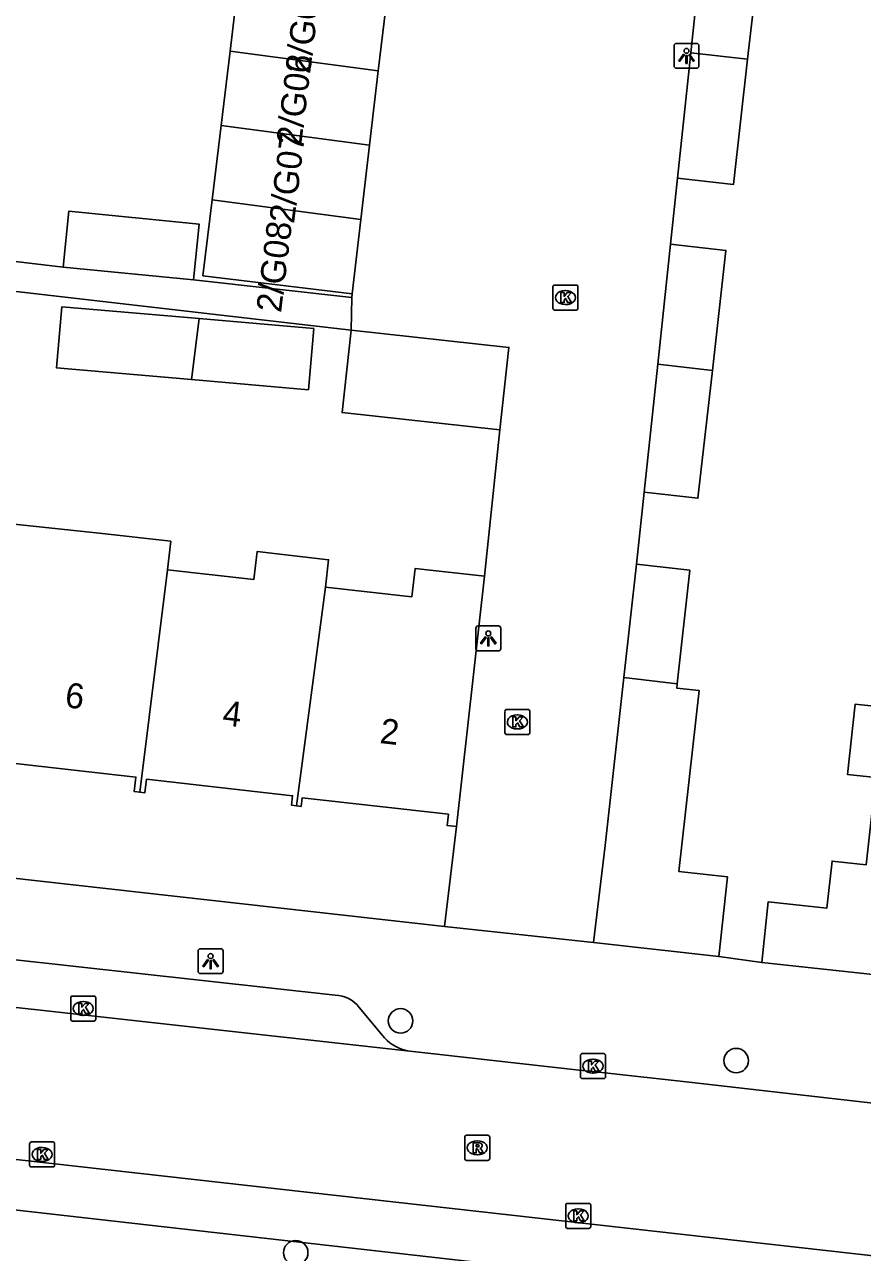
# Model space of a CAD drawing. Extents: x 162082 to 163393, y 388091 to 388632.
# Drawn here: x 162920.79 to 162954.3, y 388448.74 to 388497.83 of the extents above; entities that cross this region are included whole.
import ezdxf

# ---------------------------------------------------------------- set-up
doc = ezdxf.new("R2010")
doc.units = 0
for name, color, linetype in [('IMGEO_Boom', 7, 'Continuous'), ('IMGEO_Kolk', 7, 'Continuous'), ('IMGEO_Lichtpunt', 7, 'Continuous'), ('IMGEO_Pand', 7, 'Continuous'), ('IMGEO_Pand_nummerreeks', 7, 'Continuous'), ('IMGEO_Rijbaan_lokaal_open', 7, 'Continuous'), ('IMGEO_Rioolput', 7, 'Continuous'), ('IMGEO_Voetpad_open', 7, 'Continuous')]:
    doc.layers.add(name, color=color, linetype=linetype)

msp = doc.modelspace()

# ---------------------------------------------------------------- linework, layer by layer
at = {"layer": 'IMGEO_Boom'}
for centre in [(162935.83, 388457.998), (162949.253, 388456.41), (162931.639, 388448.731)]:
    msp.add_circle(centre, 0.489, dxfattribs=at)
at = {"layer": 'IMGEO_Kolk'}
for p, q in [((162941.925, 388486.486), (162941.925, 388487.338)), ((162942, 388487.412), (162942.852, 388487.412)), ((162942.413, 388487.192), (162942.438, 388487.192)), ((162942.926, 388487.338), (162942.926, 388486.486)), ((162942.852, 388486.412), (162942, 388486.412)), ((162942.436, 388486.632), (162942.411, 388486.632)), ((162940.001, 388469.52), (162940.001, 388470.372)), ((162940.076, 388470.446), (162940.928, 388470.446)), ((162940.489, 388470.226), (162940.514, 388470.226)), ((162941.002, 388470.372), (162941.002, 388469.52)), ((162940.512, 388469.666), (162940.487, 388469.666)), ((162940.928, 388469.446), (162940.076, 388469.446)), ((162922.641, 388458.065), (162922.641, 388458.917)), ((162922.716, 388458.991), (162923.568, 388458.991)), ((162923.129, 388458.771), (162923.154, 388458.771)), ((162923.642, 388458.917), (162923.642, 388458.065)), ((162923.152, 388458.211), (162923.127, 388458.211)), ((162923.568, 388457.991), (162922.716, 388457.991)), ((162943.025, 388455.763), (162943.025, 388456.615)), ((162943.1, 388456.689), (162943.952, 388456.689)), ((162943.513, 388456.469), (162943.538, 388456.469)), ((162944.026, 388456.615), (162944.026, 388455.763)), ((162943.536, 388455.909), (162943.511, 388455.909)), ((162943.952, 388455.689), (162943.1, 388455.689)), ((162920.996, 388452.233), (162920.996, 388453.085)), ((162921.071, 388453.159), (162921.923, 388453.159)), ((162921.484, 388452.939), (162921.509, 388452.939)), ((162921.997, 388453.085), (162921.997, 388452.233)), ((162921.507, 388452.379), (162921.482, 388452.379)), ((162921.923, 388452.159), (162921.071, 388452.159)), ((162942.434, 388449.775), (162942.434, 388450.627)), ((162942.509, 388450.701), (162943.361, 388450.701)), ((162942.922, 388450.481), (162942.947, 388450.481)), ((162943.435, 388450.627), (162943.435, 388449.775)), ((162942.945, 388449.921), (162942.92, 388449.921)), ((162943.361, 388449.701), (162942.509, 388449.701))]:
    msp.add_line(p, q, dxfattribs=at)
for points in [[(162941.925, 388486.486), (162941.925, 388487.338)], [(162942, 388487.412), (162942.852, 388487.412)], [(162942.926, 388487.338), (162942.926, 388486.486)], [(162942.246, 388487.112), (162942.369, 388487.112), (162942.369, 388486.961), (162942.499, 388487.112), (162942.663, 388487.112), (162942.517, 388486.961), (162942.67, 388486.712), (162942.518, 388486.712), (162942.433, 388486.876), (162942.369, 388486.809), (162942.369, 388486.712), (162942.246, 388486.712), (162942.246, 388487.112)], [(162942.852, 388486.412), (162942, 388486.412)], [(162940.001, 388469.52), (162940.001, 388470.372)], [(162940.076, 388470.446), (162940.928, 388470.446)], [(162940.322, 388470.146), (162940.445, 388470.146), (162940.445, 388469.995), (162940.575, 388470.146), (162940.739, 388470.146), (162940.593, 388469.995), (162940.746, 388469.746), (162940.594, 388469.746), (162940.509, 388469.91), (162940.445, 388469.843), (162940.445, 388469.746), (162940.322, 388469.746), (162940.322, 388470.146)], [(162941.002, 388470.372), (162941.002, 388469.52)], [(162940.928, 388469.446), (162940.076, 388469.446)], [(162922.641, 388458.065), (162922.641, 388458.917)], [(162922.716, 388458.991), (162923.568, 388458.991)], [(162922.962, 388458.691), (162923.085, 388458.691), (162923.085, 388458.54), (162923.215, 388458.691), (162923.379, 388458.691), (162923.233, 388458.54), (162923.386, 388458.291), (162923.234, 388458.291), (162923.149, 388458.455), (162923.085, 388458.388), (162923.085, 388458.291), (162922.962, 388458.291), (162922.962, 388458.691)], [(162923.642, 388458.917), (162923.642, 388458.065)], [(162923.568, 388457.991), (162922.716, 388457.991)], [(162943.025, 388455.763), (162943.025, 388456.615)], [(162943.1, 388456.689), (162943.952, 388456.689)], [(162943.346, 388456.389), (162943.469, 388456.389), (162943.469, 388456.238), (162943.599, 388456.389), (162943.763, 388456.389), (162943.617, 388456.238), (162943.77, 388455.989), (162943.618, 388455.989), (162943.533, 388456.153), (162943.469, 388456.086), (162943.469, 388455.989), (162943.346, 388455.989), (162943.346, 388456.389)], [(162944.026, 388456.615), (162944.026, 388455.763)], [(162943.952, 388455.689), (162943.1, 388455.689)], [(162920.996, 388452.233), (162920.996, 388453.085)], [(162921.071, 388453.159), (162921.923, 388453.159)], [(162921.317, 388452.859), (162921.44, 388452.859), (162921.44, 388452.708), (162921.57, 388452.859), (162921.734, 388452.859), (162921.588, 388452.708), (162921.741, 388452.459), (162921.589, 388452.459), (162921.504, 388452.623), (162921.44, 388452.556), (162921.44, 388452.459), (162921.317, 388452.459), (162921.317, 388452.859)], [(162921.997, 388453.085), (162921.997, 388452.233)], [(162921.923, 388452.159), (162921.071, 388452.159)], [(162942.434, 388449.775), (162942.434, 388450.627)], [(162942.509, 388450.701), (162943.361, 388450.701)], [(162942.755, 388450.401), (162942.878, 388450.401), (162942.878, 388450.25), (162943.008, 388450.401), (162943.172, 388450.401), (162943.026, 388450.25), (162943.179, 388450.001), (162943.027, 388450.001), (162942.942, 388450.165), (162942.878, 388450.098), (162942.878, 388450.001), (162942.755, 388450.001), (162942.755, 388450.401)], [(162943.435, 388450.627), (162943.435, 388449.775)], [(162943.361, 388449.701), (162942.509, 388449.701)]]:
    msp.add_lwpolyline(points, dxfattribs=at)
for centre, start, end in [((162942.002, 388487.336), 91.552, 178.448), ((162942.002, 388487.336), 91.552, 178.448), ((162942.85, 388487.336), 1.552, 88.448), ((162942.85, 388487.336), 1.552, 88.448), ((162942.002, 388486.488), 181.552, 268.448), ((162942.002, 388486.488), 181.552, 268.448), ((162942.85, 388486.488), 271.552, 358.448), ((162942.85, 388486.488), 271.552, 358.448), ((162940.078, 388470.37), 91.552, 178.448), ((162940.078, 388470.37), 91.552, 178.448), ((162940.926, 388470.37), 1.552, 88.448), ((162940.926, 388470.37), 1.552, 88.448), ((162940.078, 388469.522), 181.552, 268.448), ((162940.078, 388469.522), 181.552, 268.448), ((162940.926, 388469.522), 271.552, 358.448), ((162940.926, 388469.522), 271.552, 358.448), ((162922.718, 388458.915), 91.552, 178.448), ((162922.718, 388458.915), 91.552, 178.448), ((162923.566, 388458.915), 1.552, 88.448), ((162923.566, 388458.915), 1.552, 88.448), ((162922.718, 388458.067), 181.552, 268.448), ((162922.718, 388458.067), 181.552, 268.448), ((162923.566, 388458.067), 271.552, 358.448), ((162923.566, 388458.067), 271.552, 358.448), ((162943.102, 388456.613), 91.552, 178.448), ((162943.102, 388456.613), 91.552, 178.448), ((162943.95, 388456.613), 1.552, 88.448), ((162943.95, 388456.613), 1.552, 88.448), ((162943.102, 388455.765), 181.552, 268.448), ((162943.102, 388455.765), 181.552, 268.448), ((162943.95, 388455.765), 271.552, 358.448), ((162943.95, 388455.765), 271.552, 358.448), ((162921.073, 388453.083), 91.552, 178.448), ((162921.073, 388453.083), 91.552, 178.448), ((162921.921, 388453.083), 1.552, 88.448), ((162921.921, 388453.083), 1.552, 88.448), ((162921.073, 388452.235), 181.552, 268.448), ((162921.073, 388452.235), 181.552, 268.448), ((162921.921, 388452.235), 271.552, 358.448), ((162921.921, 388452.235), 271.552, 358.448), ((162942.511, 388450.625), 91.552, 178.448), ((162942.511, 388450.625), 91.552, 178.448), ((162943.359, 388450.625), 1.552, 88.448), ((162943.359, 388450.625), 1.552, 88.448), ((162942.511, 388449.777), 181.552, 268.448), ((162942.511, 388449.777), 181.552, 268.448), ((162943.359, 388449.777), 271.552, 358.448), ((162943.359, 388449.777), 271.552, 358.448)]:
    msp.add_arc(centre, 0.0765, start, end, dxfattribs=at)
for centre, major_axis, ratio, start_param, end_param in [((162942.412, 388486.912), (-0.387, 0.002), 0.722429, 4.712389, 7.853982), ((162942.437, 388486.912), (-0.39, 0.002), 0.717154, 1.570796, 4.712389), ((162940.488, 388469.946), (-0.387, 0.002), 0.722429, 4.712389, 7.853982), ((162940.513, 388469.946), (-0.39, 0.002), 0.717154, 1.570796, 4.712389), ((162923.128, 388458.491), (-0.387, 0.002), 0.722429, 4.712389, 7.853982), ((162923.153, 388458.491), (-0.39, 0.002), 0.717154, 1.570796, 4.712389), ((162943.512, 388456.189), (-0.387, 0.002), 0.722429, 4.712389, 7.853982), ((162943.537, 388456.189), (-0.39, 0.002), 0.717154, 1.570796, 4.712389), ((162921.483, 388452.659), (-0.387, 0.002), 0.722429, 4.712389, 7.853982), ((162921.508, 388452.659), (-0.39, 0.002), 0.717154, 1.570796, 4.712389), ((162942.921, 388450.201), (-0.387, 0.002), 0.722429, 4.712389, 7.853982), ((162942.946, 388450.201), (-0.39, 0.002), 0.717154, 1.570796, 4.712389)]:
    msp.add_ellipse(centre, major_axis=major_axis, ratio=ratio, start_param=start_param, end_param=end_param, dxfattribs=at)
at = {"layer": 'IMGEO_Lichtpunt'}
for p, q in [((162946.767, 388496.979), (162946.767, 388496.172)), ((162946.767, 388496.979), (162946.767, 388496.172)), ((162947.669, 388497.074), (162946.861, 388497.074)), ((162947.669, 388497.074), (162946.861, 388497.074)), ((162947.763, 388496.172), (162947.763, 388496.979)), ((162947.763, 388496.172), (162947.763, 388496.979)), ((162946.861, 388496.078), (162947.669, 388496.078)), ((162946.861, 388496.078), (162947.669, 388496.078)), ((162938.841, 388473.69), (162938.841, 388472.883)), ((162938.841, 388473.69), (162938.841, 388472.883)), ((162939.743, 388473.785), (162938.935, 388473.785)), ((162939.743, 388473.785), (162938.935, 388473.785)), ((162939.837, 388472.883), (162939.837, 388473.69)), ((162939.837, 388472.883), (162939.837, 388473.69)), ((162938.935, 388472.789), (162939.743, 388472.789)), ((162938.935, 388472.789), (162939.743, 388472.789)), ((162927.736, 388460.788), (162927.736, 388459.981)), ((162927.736, 388460.788), (162927.736, 388459.981)), ((162928.638, 388460.883), (162927.83, 388460.883)), ((162928.638, 388460.883), (162927.83, 388460.883)), ((162928.732, 388459.981), (162928.732, 388460.788)), ((162928.732, 388459.981), (162928.732, 388460.788)), ((162927.83, 388459.887), (162928.638, 388459.887)), ((162927.83, 388459.887), (162928.638, 388459.887))]:
    msp.add_line(p, q, dxfattribs=at)
for points in [[(162947.141, 388496.643), (162947.18, 388496.615), (162946.992, 388496.353), (162946.954, 388496.38), (162947.141, 388496.643)], [(162947.243, 388496.595), (162947.29, 388496.595), (162947.29, 388496.273), (162947.243, 388496.273), (162947.243, 388496.595)], [(162947.353, 388496.615), (162947.391, 388496.642), (162947.578, 388496.38), (162947.539, 388496.352), (162947.353, 388496.615)], [(162939.215, 388473.354), (162939.254, 388473.326), (162939.066, 388473.064), (162939.028, 388473.091), (162939.215, 388473.354)], [(162939.317, 388473.306), (162939.364, 388473.306), (162939.364, 388472.984), (162939.317, 388472.984), (162939.317, 388473.306)], [(162939.427, 388473.326), (162939.465, 388473.353), (162939.652, 388473.091), (162939.613, 388473.063), (162939.427, 388473.326)], [(162928.11, 388460.452), (162928.149, 388460.424), (162927.961, 388460.162), (162927.923, 388460.189), (162928.11, 388460.452)], [(162928.212, 388460.404), (162928.259, 388460.404), (162928.259, 388460.082), (162928.212, 388460.082), (162928.212, 388460.404)], [(162928.322, 388460.424), (162928.36, 388460.451), (162928.547, 388460.189), (162928.508, 388460.161), (162928.322, 388460.424)]]:
    msp.add_lwpolyline(points, dxfattribs=at)
for centre in [(162947.266, 388496.777), (162939.34, 388473.488), (162928.235, 388460.586)]:
    msp.add_circle(centre, 0.0994, dxfattribs=at)
for centre, start, end in [((162946.861, 388496.979), 90, 180), ((162946.861, 388496.979), 90, 180), ((162947.669, 388496.979), 0, 90), ((162947.669, 388496.979), 0, 90), ((162946.861, 388496.172), 180, 270), ((162946.861, 388496.172), 180, 270), ((162947.669, 388496.172), 270, 0), ((162947.669, 388496.172), 270, 360), ((162938.935, 388473.69), 90, 180), ((162938.935, 388473.69), 90, 180), ((162939.743, 388473.69), 0, 90), ((162939.743, 388473.69), 0, 90), ((162938.935, 388472.883), 180, 270), ((162938.935, 388472.883), 180, 270), ((162939.743, 388472.883), 270, 0), ((162939.743, 388472.883), 270, 360), ((162927.83, 388460.788), 90, 180), ((162927.83, 388460.788), 90, 180), ((162928.638, 388460.788), 0, 90), ((162928.638, 388460.788), 0, 90), ((162927.83, 388459.981), 180, 270), ((162927.83, 388459.981), 180, 270), ((162928.638, 388459.981), 270, 0), ((162928.638, 388459.981), 270, 360)]:
    msp.add_arc(centre, 0.0946, start, end, dxfattribs=at)
at = {"layer": 'IMGEO_Pand'}
for points in [[(162947.434, 388496.691), (162947.785, 388500), (162947.954, 388501.591)], [(162947.954, 388501.591), (162950.262, 388501.33), (162950.112, 388500), (162949.709, 388496.438)], [(162935.291, 388498.943), (162934.941, 388495.971)], [(162929.012, 388496.762), (162929.23, 388498.563)], [(162928.653, 388493.791), (162929.012, 388496.762)], [(162929.012, 388496.762), (162934.941, 388495.971)], [(162946.902, 388491.686), (162947.434, 388496.691)], [(162947.434, 388496.691), (162949.709, 388496.438)], [(162949.709, 388496.438), (162949.143, 388491.433), (162946.902, 388491.686)], [(162934.941, 388495.971), (162934.59, 388492.999)], [(162928.294, 388490.821), (162928.653, 388493.791)], [(162928.653, 388493.791), (162934.59, 388492.999)], [(162934.59, 388492.999), (162934.24, 388490.028)], [(162933.89, 388487.061), (162927.926, 388487.782), (162928.294, 388490.821)], [(162934.24, 388490.028), (162928.294, 388490.821)], [(162922.341, 388488.13), (162922.56, 388490.361), (162927.773, 388489.848), (162927.554, 388487.617)], [(162934.24, 388490.028), (162933.89, 388487.061)], [(162946.113, 388484.252), (162946.622, 388489.051)], [(162946.622, 388489.051), (162948.845, 388488.8), (162948.303, 388484.004)], [(162927.554, 388487.617), (162922.341, 388488.13)], [(162927.466, 388483.635), (162922.078, 388484.103), (162922.29, 388486.547), (162927.771, 388486.071)], [(162927.466, 388483.635), (162927.771, 388486.071)], [(162927.771, 388486.071), (162932.36, 388485.672), (162932.148, 388483.228), (162927.466, 388483.635)], [(162939.801, 388481.623), (162933.495, 388482.314), (162933.857, 388485.612)], [(162933.857, 388485.612), (162940.163, 388484.92), (162939.801, 388481.623)], [(162945.57, 388479.136), (162946.113, 388484.252)], [(162946.113, 388484.252), (162948.303, 388484.004)], [(162948.303, 388484.004), (162947.725, 388478.893), (162945.57, 388479.136)], [(162920.381, 388477.851), (162923.777, 388477.496), (162926.641, 388477.172), (162926.513, 388476.035)], [(162926.513, 388476.035), (162929.964, 388475.645), (162930.09, 388476.759), (162932.955, 388476.435), (162932.831, 388475.341)], [(162925.398, 388467.14), (162926.513, 388476.035)], [(162932.831, 388475.341), (162936.288, 388474.95), (162936.416, 388476.083), (162939.192, 388475.769)], [(162944.757, 388471.719), (162945.263, 388476.25)], [(162945.263, 388476.25), (162947.399, 388476.012), (162946.893, 388471.475)], [(162939.192, 388475.769), (162938.062, 388465.768)], [(162932.831, 388475.341), (162931.676, 388466.593)], [(162943.553, 388461.129), (162944.008, 388465.015), (162944.757, 388471.719)], [(162944.757, 388471.719), (162946.893, 388471.475)], [(162946.893, 388471.475), (162946.874, 388471.302), (162947.771, 388471.202), (162946.964, 388463.967), (162948.912, 388463.75), (162948.558, 388460.57)], [(162950.273, 388460.333), (162950.537, 388462.759), (162952.884, 388462.505), (162953.088, 388464.384), (162954.447, 388464.237), (162954.831, 388467.725), (162953.701, 388467.849), (162954.009, 388470.657), (162955.142, 388470.533)], [(162925.398, 388467.14), (162925.184, 388467.164), (162925.25, 388467.741), (162919.474, 388468.394), (162919.419, 388467.911), (162919.225, 388467.933)], [(162931.676, 388466.593), (162931.472, 388466.616), (162931.515, 388466.997), (162925.671, 388467.658), (162925.61, 388467.116), (162925.398, 388467.14)], [(162938.062, 388465.768), (162937.693, 388465.81), (162937.743, 388466.255), (162931.899, 388466.916), (162931.86, 388466.572), (162931.676, 388466.593)], [(162948.558, 388460.57), (162943.553, 388461.129)], [(162959.667, 388459.314), (162950.273, 388460.333)]]:
    msp.add_lwpolyline(points, dxfattribs=at)
at = {"layer": 'IMGEO_Rijbaan_lokaal_open'}
for points in [[(162946.902, 388491.686), (162946.622, 388489.051)], [(162933.857, 388485.612), (162933.887, 388486.915)], [(162933.89, 388487.061), (162933.887, 388486.915)], [(162939.192, 388475.769), (162939.801, 388481.623)], [(162945.57, 388479.136), (162945.263, 388476.25)], [(162937.585, 388461.764), (162938.062, 388465.768)], [(162936.199, 388456.79), (162886.097, 388462.347)], [(162943.553, 388461.129), (162937.585, 388461.764)], [(162936.199, 388456.79), (162937.278, 388456.67), (162942.976, 388456.033), (162943.878, 388455.932), (162947.378, 388455.541), (162967.209, 388453.279)], [(162904.56, 388454.238), (163001.108, 388443.395)]]:
    msp.add_lwpolyline(points, dxfattribs=at)
at = {"layer": 'IMGEO_Rioolput'}
for p, q in [((162938.398, 388452.496), (162938.398, 388453.348)), ((162938.473, 388453.422), (162939.325, 388453.422)), ((162939.399, 388453.348), (162939.399, 388452.496)), ((162938.886, 388453.202), (162938.911, 388453.202)), ((162939.325, 388452.422), (162938.473, 388452.422)), ((162938.909, 388452.642), (162938.884, 388452.642))]:
    msp.add_line(p, q, dxfattribs=at)
for points in [[(162938.398, 388452.496), (162938.398, 388453.348)], [(162938.473, 388453.422), (162939.325, 388453.422)], [(162939.399, 388453.348), (162939.399, 388452.496)], [(162938.987, 388453.12), (162938.735, 388453.122), (162938.735, 388452.722)], [(162938.735, 388452.722), (162938.859, 388452.722), (162938.859, 388452.884), (162938.87, 388452.884)], [(162938.913, 388453.041), (162938.859, 388453.041), (162938.859, 388452.96)], [(162938.859, 388452.96), (162938.911, 388452.96)], [(162938.917, 388452.855), (162938.988, 388452.722), (162939.128, 388452.722), (162939.063, 388452.848)], [(162939.325, 388452.422), (162938.473, 388452.422)]]:
    msp.add_lwpolyline(points, dxfattribs=at)
for centre, radius, start, end in [((162938.475, 388453.346), 0.0765, 91.552, 178.448), ((162938.475, 388453.346), 0.0765, 91.552, 178.448), ((162939.323, 388453.346), 0.0765, 1.552, 88.448), ((162939.323, 388453.346), 0.0765, 1.552, 88.448), ((162938.869, 388452.831), 0.0533, 26.0293, 88.6989), ((162938.895, 388453.149), 0.19, 274.7715, 282.9687), ((162938.919, 388452.945), 0.0964, 77.0061, 93.1865), ((162938.933, 388453.002), 0.0378, 276.6634, 79.6772), ((162938.986, 388453.01), 0.109, 350.3612, 89.416), ((162938.984, 388453.01), 0.112, 277.5842, 350.9817), ((162938.968, 388452.795), 0.108, 29.5134, 73.7905), ((162938.475, 388452.498), 0.0765, 181.552, 268.448), ((162938.475, 388452.498), 0.0765, 181.552, 268.448), ((162939.323, 388452.498), 0.0765, 271.552, 358.448), ((162939.323, 388452.498), 0.0765, 271.552, 358.448)]:
    msp.add_arc(centre, radius, start, end, dxfattribs=at)
for centre, major_axis, ratio, start_param, end_param in [((162938.885, 388452.922), (-0.387, 0.002), 0.722429, 4.712389, 7.853982), ((162938.91, 388452.922), (-0.39, 0.002), 0.717154, 1.570796, 4.712389)]:
    msp.add_ellipse(centre, major_axis=major_axis, ratio=ratio, start_param=start_param, end_param=end_param, dxfattribs=at)
at = {"layer": 'IMGEO_Voetpad_open'}
for points in [[(162933.857, 388485.612), (162887.885, 388490.912)], [(162922.341, 388488.13), (162919.974, 388488.402)], [(162933.887, 388486.915), (162927.554, 388487.617)], [(162937.585, 388461.764), (162885.189, 388467.652)], [(162888.827, 388463.931), (162933.209, 388459.029)], [(162950.273, 388460.333), (162948.558, 388460.57)], [(162934.181, 388458.532), (162935.19, 388457.324)], [(162907.902, 388451.85), (162984.007, 388443.238), (162987.61, 388442.83), (162997.358, 388441.727)]]:
    msp.add_lwpolyline(points, dxfattribs=at)
for centre, radius, start, end in [((162933.182, 388457.777), 1.253, 37.0866, 88.7506), ((162936.419, 388458.426), 1.651, 221.8827, 262.3384)]:
    msp.add_arc(centre, radius, start, end, dxfattribs=at)

# ---------------------------------------------------------------- texts
at = {"layer": 'IMGEO_Pand_nummerreeks'}
for s, rotation, p in [('2/G05', 82.9297, (162932.21, 388495.834)), ('2/G06', 82.9297, (162931.854, 388492.96)), ('2/G07', 82.9297, (162931.568, 388489.844)), ('2/G08', 82.9297, (162931.049, 388486.283)), ('6', 353.5104, (162922.381, 388470.538)), ('4', 353.5104, (162928.678, 388469.822)), ('2', 353.5104, (162934.973, 388469.107))]:
    msp.add_text(s, height=1, rotation=rotation, dxfattribs=at).set_placement(p)

doc.saveas('drawing.dxf')
